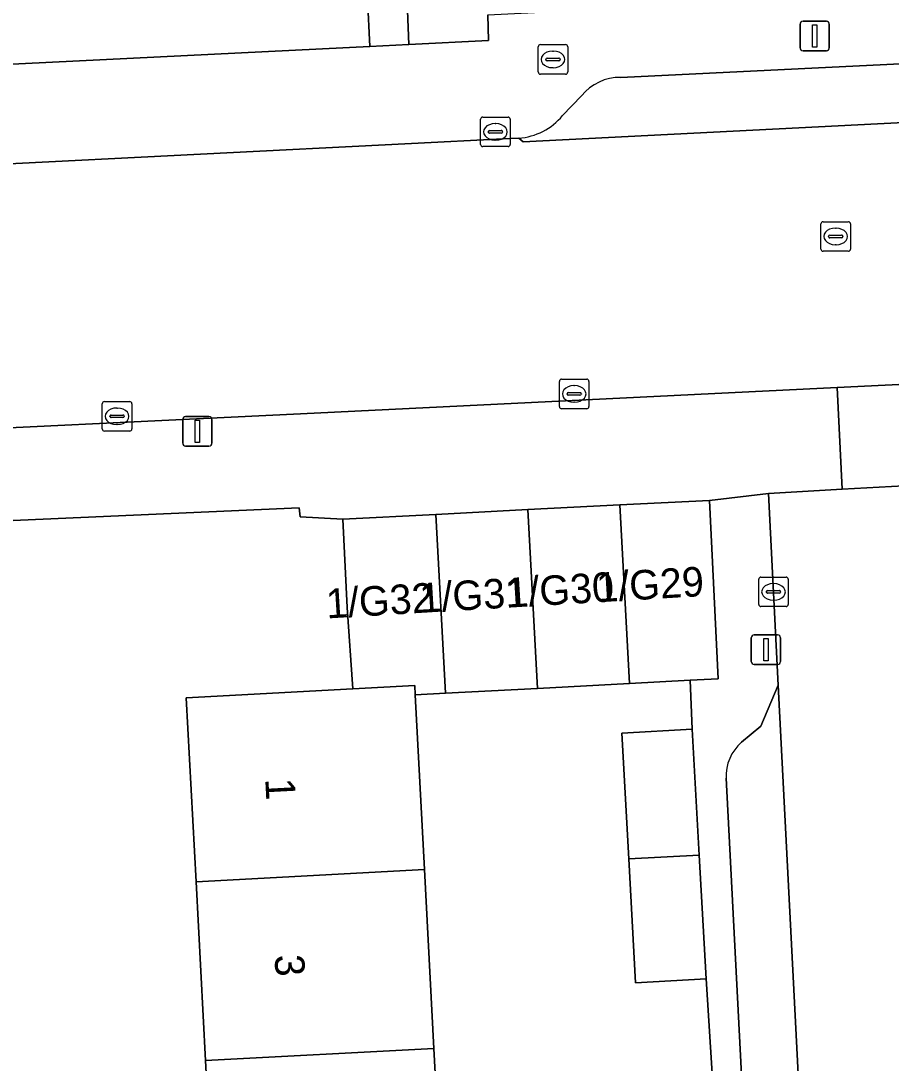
# Model space of a CAD drawing. Extents: x 161084 to 161928, y 385354 to 386522.
# Drawn here: x 161364.66 to 161394.1, y 385718 to 385753.28 of the extents above; entities that cross this region are included whole.
import ezdxf

# ---------------------------------------------------------------- set-up
doc = ezdxf.new("R2010")
doc.units = 0
for name, color, linetype in [('IMGEO_Brandkraan', 7, 'Continuous'), ('IMGEO_Erf', 7, 'Continuous'), ('IMGEO_Kolk', 7, 'Continuous'), ('IMGEO_Lichtmast', 7, 'Continuous'), ('IMGEO_Pand', 7, 'Continuous'), ('IMGEO_Pand_nummerreeks', 7, 'Continuous'), ('IMGEO_Parkeervlak_open', 7, 'Continuous'), ('IMGEO_Rijbaan_lokaal_gesloten', 7, 'Continuous'), ('IMGEO_Rijbaan_lokaal_open', 7, 'Continuous'), ('IMGEO_Rioolput', 7, 'Continuous'), ('IMGEO_Voetpad_open', 7, 'Continuous')]:
    doc.layers.add(name, color=color, linetype=linetype)

msp = doc.modelspace()

# ---------------------------------------------------------------- linework, layer by layer
at = {"layer": 'IMGEO_Brandkraan'}
for p, q in [((161382.162, 385751.55), (161382.162, 385752.402)), ((161382.237, 385752.476), (161383.089, 385752.476)), ((161382.65, 385752.256), (161382.675, 385752.256)), ((161383.163, 385752.402), (161383.163, 385751.55)), ((161382.421, 385751.97), (161382.421, 385751.982)), ((161382.859, 385751.933), (161382.461, 385751.933)), ((161382.464, 385752.019), (161382.862, 385752.019)), ((161382.905, 385751.982), (161382.905, 385751.97)), ((161383.089, 385751.476), (161382.237, 385751.476)), ((161382.673, 385751.696), (161382.648, 385751.696))]:
    msp.add_line(p, q, dxfattribs=at)
for points in [[(161382.162, 385751.55), (161382.162, 385752.402)], [(161382.237, 385752.476), (161383.089, 385752.476)], [(161383.163, 385752.402), (161383.163, 385751.55)], [(161383.089, 385751.476), (161382.237, 385751.476)]]:
    msp.add_lwpolyline(points, dxfattribs=at)
for centre, radius, start, end in [((161382.239, 385752.4), 0.0765, 91.552, 178.448), ((161382.239, 385752.4), 0.0765, 91.552, 178.448), ((161383.087, 385752.4), 0.0765, 1.552, 88.448), ((161383.087, 385752.4), 0.0765, 1.552, 88.448), ((161382.461, 385751.979), 0.0403, 85.8775, 175.7526), ((161382.458, 385751.969), 0.0366, 178.938, 274.7102), ((161382.862, 385751.976), 0.043, 264.8664, 352.4533), ((161382.866, 385751.981), 0.0386, 1.7309, 96.639), ((161382.239, 385751.552), 0.0765, 181.552, 268.448), ((161382.239, 385751.552), 0.0765, 181.552, 268.448), ((161383.087, 385751.552), 0.0765, 271.552, 358.448), ((161383.087, 385751.552), 0.0765, 271.552, 358.448)]:
    msp.add_arc(centre, radius, start, end, dxfattribs=at)
for centre, major_axis, ratio, start_param, end_param in [((161382.649, 385751.976), (-0.387, 0.002), 0.722429, 4.712389, 7.853982), ((161382.674, 385751.976), (-0.39, 0.002), 0.717154, 1.570796, 4.712389)]:
    msp.add_ellipse(centre, major_axis=major_axis, ratio=ratio, start_param=start_param, end_param=end_param, dxfattribs=at)
at = {"layer": 'IMGEO_Erf'}
for points in [[(161453.458, 385766.91), (161450.05, 385766.74), (161450.26, 385762.549), (161443.836, 385762.228), (161437.572, 385761.916), (161431.308, 385761.603), (161425.044, 385761.29), (161418.78, 385760.978), (161412.515, 385760.665), (161406.251, 385760.353), (161399.987, 385760.04), (161393.723, 385759.727), (161387.459, 385759.415), (161381.035, 385759.094), (161380.824, 385763.331), (161377.364, 385763.158), (161377.787, 385752.478), (161380.483, 385752.611), (161380.46, 385753.49), (161418.265, 385755.389), (161453.943, 385757.182)], [(161376.23, 385757.297), (161370.105, 385756.987), (161364.158, 385756.686), (161358.21, 385756.385), (161352.263, 385756.083), (161346.316, 385755.782), (161340.368, 385755.481), (161334.421, 385755.18), (161328.473, 385754.879), (161322.352, 385754.569), (161322.529, 385749.751), (161327.583, 385750), (161376.462, 385752.413)]]:
    msp.add_lwpolyline(points, close=True, dxfattribs=at)
for points in [[(161371.228, 385712.042), (161370.908, 385718.094), (161370.588, 385724.145), (161370.258, 385730.371), (161375.892, 385730.669), (161375.703, 385733.42), (161375.549, 385736.416), (161374.107, 385736.499), (161374.079, 385736.804), (161361.079, 385736.228)], [(161388.083, 385717.128), (161387.843, 385720.857), (161385.457, 385720.724), (161385.224, 385724.918), (161384.988, 385729.175), (161387.375, 385729.308), (161387.301, 385730.962), (161385.248, 385730.853), (161382.135, 385730.689), (161379.021, 385730.524), (161378, 385730.47), (161378.313, 385724.553), (161378.634, 385718.502), (161378.954, 385712.45)]]:
    msp.add_lwpolyline(points, dxfattribs=at)
at = {"layer": 'IMGEO_Kolk'}
for p, q in [((161380.215, 385749.098), (161380.215, 385749.95)), ((161380.29, 385750.024), (161381.142, 385750.024)), ((161380.703, 385749.804), (161380.728, 385749.804)), ((161381.216, 385749.95), (161381.216, 385749.098)), ((161380.474, 385749.518), (161380.474, 385749.53)), ((161380.912, 385749.481), (161380.514, 385749.481)), ((161380.517, 385749.567), (161380.915, 385749.567)), ((161380.958, 385749.53), (161380.958, 385749.518)), ((161381.142, 385749.024), (161380.29, 385749.024)), ((161380.726, 385749.244), (161380.701, 385749.244)), ((161382.879, 385740.228), (161382.879, 385741.08)), ((161382.954, 385741.154), (161383.806, 385741.154)), ((161383.367, 385740.934), (161383.392, 385740.934)), ((161383.88, 385741.08), (161383.88, 385740.228)), ((161383.138, 385740.648), (161383.138, 385740.66)), ((161383.576, 385740.611), (161383.178, 385740.611)), ((161383.181, 385740.697), (161383.579, 385740.697)), ((161383.622, 385740.66), (161383.622, 385740.648)), ((161367.416, 385739.47), (161367.416, 385740.322)), ((161367.491, 385740.396), (161368.343, 385740.396)), ((161367.904, 385740.176), (161367.929, 385740.176)), ((161368.417, 385740.322), (161368.417, 385739.47)), ((161383.39, 385740.374), (161383.365, 385740.374)), ((161367.675, 385739.89), (161367.675, 385739.902)), ((161368.113, 385739.853), (161367.715, 385739.853)), ((161367.718, 385739.939), (161368.116, 385739.939)), ((161368.159, 385739.902), (161368.159, 385739.89)), ((161383.806, 385740.154), (161382.954, 385740.154)), ((161367.927, 385739.616), (161367.902, 385739.616)), ((161368.343, 385739.396), (161367.491, 385739.396)), ((161389.621, 385733.529), (161389.621, 385734.381)), ((161389.696, 385734.455), (161390.548, 385734.455)), ((161390.109, 385734.235), (161390.134, 385734.235)), ((161390.622, 385734.381), (161390.622, 385733.529)), ((161389.88, 385733.949), (161389.88, 385733.961)), ((161390.318, 385733.912), (161389.92, 385733.912)), ((161389.923, 385733.998), (161390.321, 385733.998)), ((161390.364, 385733.961), (161390.364, 385733.949)), ((161390.132, 385733.675), (161390.107, 385733.675)), ((161390.548, 385733.455), (161389.696, 385733.455))]:
    msp.add_line(p, q, dxfattribs=at)
for points in [[(161380.215, 385749.098), (161380.215, 385749.95)], [(161380.29, 385750.024), (161381.142, 385750.024)], [(161381.216, 385749.95), (161381.216, 385749.098)], [(161381.142, 385749.024), (161380.29, 385749.024)], [(161382.879, 385740.228), (161382.879, 385741.08)], [(161382.954, 385741.154), (161383.806, 385741.154)], [(161383.88, 385741.08), (161383.88, 385740.228)], [(161367.416, 385739.47), (161367.416, 385740.322)], [(161367.491, 385740.396), (161368.343, 385740.396)], [(161368.417, 385740.322), (161368.417, 385739.47)], [(161383.806, 385740.154), (161382.954, 385740.154)], [(161368.343, 385739.396), (161367.491, 385739.396)], [(161389.621, 385733.529), (161389.621, 385734.381)], [(161389.696, 385734.455), (161390.548, 385734.455)], [(161390.622, 385734.381), (161390.622, 385733.529)], [(161390.548, 385733.455), (161389.696, 385733.455)]]:
    msp.add_lwpolyline(points, dxfattribs=at)
for centre, radius, start, end in [((161380.292, 385749.948), 0.0765, 91.552, 178.448), ((161380.292, 385749.948), 0.0765, 91.552, 178.448), ((161381.14, 385749.948), 0.0765, 1.552, 88.448), ((161381.14, 385749.948), 0.0765, 1.552, 88.448), ((161380.514, 385749.527), 0.0403, 85.8775, 175.7526), ((161380.511, 385749.517), 0.0366, 178.938, 274.7102), ((161380.915, 385749.524), 0.043, 264.8664, 352.4533), ((161380.919, 385749.529), 0.0386, 1.7309, 96.639), ((161380.292, 385749.1), 0.0765, 181.552, 268.448), ((161380.292, 385749.1), 0.0765, 181.552, 268.448), ((161381.14, 385749.1), 0.0765, 271.552, 358.448), ((161381.14, 385749.1), 0.0765, 271.552, 358.448), ((161382.956, 385741.078), 0.0765, 91.552, 178.448), ((161382.956, 385741.078), 0.0765, 91.552, 178.448), ((161383.804, 385741.078), 0.0765, 1.552, 88.448), ((161383.804, 385741.078), 0.0765, 1.552, 88.448), ((161383.178, 385740.657), 0.0403, 85.8775, 175.7526), ((161383.175, 385740.647), 0.0366, 178.938, 274.7102), ((161383.579, 385740.654), 0.043, 264.8664, 352.4533), ((161383.583, 385740.659), 0.0386, 1.7309, 96.639), ((161367.493, 385740.32), 0.0765, 91.552, 178.448), ((161367.493, 385740.32), 0.0765, 91.552, 178.448), ((161368.341, 385740.32), 0.0765, 1.552, 88.448), ((161368.341, 385740.32), 0.0765, 1.552, 88.448), ((161382.956, 385740.23), 0.0765, 181.552, 268.448), ((161382.956, 385740.23), 0.0765, 181.552, 268.448), ((161383.804, 385740.23), 0.0765, 271.552, 358.448), ((161383.804, 385740.23), 0.0765, 271.552, 358.448), ((161367.715, 385739.899), 0.0403, 85.8775, 175.7526), ((161367.712, 385739.889), 0.0366, 178.938, 274.7102), ((161368.116, 385739.896), 0.043, 264.8664, 352.4533), ((161368.12, 385739.901), 0.0386, 1.7309, 96.639), ((161367.493, 385739.472), 0.0765, 181.552, 268.448), ((161367.493, 385739.472), 0.0765, 181.552, 268.448), ((161368.341, 385739.472), 0.0765, 271.552, 358.448), ((161368.341, 385739.472), 0.0765, 271.552, 358.448), ((161389.698, 385734.379), 0.0765, 91.552, 178.448), ((161389.698, 385734.379), 0.0765, 91.552, 178.448), ((161390.546, 385734.379), 0.0765, 1.552, 88.448), ((161390.546, 385734.379), 0.0765, 1.552, 88.448), ((161389.92, 385733.958), 0.0403, 85.8775, 175.7526), ((161389.917, 385733.948), 0.0366, 178.938, 274.7102), ((161390.321, 385733.955), 0.043, 264.8664, 352.4533), ((161390.325, 385733.96), 0.0386, 1.7309, 96.639), ((161389.698, 385733.531), 0.0765, 181.552, 268.448), ((161389.698, 385733.531), 0.0765, 181.552, 268.448), ((161390.546, 385733.531), 0.0765, 271.552, 358.448), ((161390.546, 385733.531), 0.0765, 271.552, 358.448)]:
    msp.add_arc(centre, radius, start, end, dxfattribs=at)
for centre, major_axis, ratio, start_param, end_param in [((161380.702, 385749.524), (-0.387, 0.002), 0.722429, 4.712389, 7.853982), ((161380.727, 385749.524), (-0.39, 0.002), 0.717154, 1.570796, 4.712389), ((161383.366, 385740.654), (-0.387, 0.002), 0.722429, 4.712389, 7.853982), ((161383.391, 385740.654), (-0.39, 0.002), 0.717154, 1.570796, 4.712389), ((161367.903, 385739.896), (-0.387, 0.002), 0.722429, 4.712389, 7.853982), ((161367.928, 385739.896), (-0.39, 0.002), 0.717154, 1.570796, 4.712389), ((161390.108, 385733.955), (-0.387, 0.002), 0.722429, 4.712389, 7.853982), ((161390.133, 385733.955), (-0.39, 0.002), 0.717154, 1.570796, 4.712389)]:
    msp.add_ellipse(centre, major_axis=major_axis, ratio=ratio, start_param=start_param, end_param=end_param, dxfattribs=at)
at = {"layer": 'IMGEO_Lichtmast'}
for p, q in [((161391.121, 385753.269), (161391.911, 385753.269)), ((161391.911, 385753.269), (161391.121, 385753.269)), ((161391.021, 385752.369), (161391.021, 385753.169)), ((161391.021, 385753.169), (161391.021, 385752.369)), ((161392.011, 385753.169), (161392.011, 385752.369)), ((161392.011, 385752.369), (161392.011, 385753.169)), ((161391.911, 385752.269), (161391.121, 385752.269)), ((161391.121, 385752.269), (161391.911, 385752.269)), ((161370.236, 385739.888), (161371.026, 385739.888)), ((161371.026, 385739.888), (161370.236, 385739.888)), ((161370.136, 385738.988), (161370.136, 385739.788)), ((161370.136, 385739.788), (161370.136, 385738.988)), ((161371.126, 385739.788), (161371.126, 385738.988)), ((161371.126, 385738.988), (161371.126, 385739.788)), ((161371.026, 385738.888), (161370.236, 385738.888)), ((161370.236, 385738.888), (161371.026, 385738.888)), ((161389.471, 385732.498), (161390.261, 385732.498)), ((161390.261, 385732.498), (161389.471, 385732.498)), ((161389.371, 385731.598), (161389.371, 385732.398)), ((161389.371, 385732.398), (161389.371, 385731.598)), ((161390.361, 385732.398), (161390.361, 385731.598)), ((161390.361, 385731.598), (161390.361, 385732.398)), ((161390.261, 385731.498), (161389.471, 385731.498)), ((161389.471, 385731.498), (161390.261, 385731.498))]:
    msp.add_line(p, q, dxfattribs=at)
for points in [[(161391.441, 385753.144), (161391.591, 385753.144), (161391.591, 385752.394), (161391.441, 385752.394), (161391.441, 385753.144)], [(161370.556, 385739.763), (161370.706, 385739.763), (161370.706, 385739.013), (161370.556, 385739.013), (161370.556, 385739.763)], [(161389.791, 385732.373), (161389.941, 385732.373), (161389.941, 385731.623), (161389.791, 385731.623), (161389.791, 385732.373)]]:
    msp.add_lwpolyline(points, dxfattribs=at)
for centre, start, end in [((161391.121, 385753.169), 90, 180), ((161391.121, 385753.169), 90, 180), ((161391.911, 385753.169), 0, 90), ((161391.911, 385753.169), 360, 90), ((161391.121, 385752.369), 180, 270), ((161391.121, 385752.369), 180, 270), ((161391.911, 385752.369), 270, 0), ((161391.911, 385752.369), 270, 0), ((161370.236, 385739.788), 90, 180), ((161370.236, 385739.788), 90, 180), ((161371.026, 385739.788), 0, 90), ((161371.026, 385739.788), 360, 90), ((161370.236, 385738.988), 180, 270), ((161370.236, 385738.988), 180, 270), ((161371.026, 385738.988), 270, 0), ((161371.026, 385738.988), 270, 0), ((161389.471, 385732.398), 90, 180), ((161389.471, 385732.398), 90, 180), ((161390.261, 385732.398), 0, 90), ((161390.261, 385732.398), 360, 90), ((161389.471, 385731.598), 180, 270), ((161389.471, 385731.598), 180, 270), ((161390.261, 385731.598), 270, 0), ((161390.261, 385731.598), 270, 0)]:
    msp.add_arc(centre, 0.1, start, end, dxfattribs=at)
at = {"layer": 'IMGEO_Pand'}
for points in [[(161387.962, 385737.051), (161384.929, 385736.896), (161385.248, 385730.853), (161387.301, 385730.962), (161388.254, 385731.012)], [(161381.815, 385736.737), (161378.701, 385736.577), (161379.021, 385730.524), (161382.135, 385730.689)], [(161384.929, 385736.896), (161381.815, 385736.737), (161382.135, 385730.689), (161385.248, 385730.853)], [(161378.701, 385736.577), (161375.549, 385736.416), (161375.703, 385733.42), (161375.892, 385730.669), (161377.984, 385730.78), (161378, 385730.47), (161379.021, 385730.524)], [(161377.984, 385730.78), (161375.892, 385730.669), (161370.258, 385730.371), (161370.588, 385724.145), (161378.313, 385724.553), (161378, 385730.47)], [(161387.375, 385729.308), (161384.988, 385729.175), (161385.224, 385724.918), (161387.611, 385725.044)], [(161387.611, 385725.044), (161385.224, 385724.918), (161385.457, 385720.724), (161387.843, 385720.857)], [(161378.634, 385718.502), (161378.313, 385724.553), (161370.588, 385724.145), (161370.908, 385718.094)], [(161370.908, 385718.094), (161371.228, 385712.042), (161378.954, 385712.45), (161378.634, 385718.502)]]:
    msp.add_lwpolyline(points, close=True, dxfattribs=at)
at = {"layer": 'IMGEO_Parkeervlak_open'}
for points in [[(161530.283, 385758.789), (161528.955, 385758.728), (161500.001, 385757.213), (161458.938, 385755.138), (161455.76, 385754.979), (161454.163, 385754.884), (161450.803, 385754.684), (161418.419, 385752.994), (161384.956, 385751.367)], [(161381.504, 385749.31), (161381.651, 385749.181), (161418.736, 385751.073), (161500.103, 385755.198)], [(161383.628, 385750.746), (161382.99, 385750.073)], [(161393.58, 385666.612), (161393.423, 385669.684), (161393.28, 385672.47), (161390.284, 385730.795), (161389.69, 385729.412), (161389.045, 385728.863)], [(161388.519, 385727.644), (161391.505, 385669.795)]]:
    msp.add_lwpolyline(points, dxfattribs=at)
for centre, radius, start, end in [((161384.928, 385749.697), 1.67, 89.0274, 141.0961), ((161381.342, 385751.454), 2.15, 274.3196, 320.0376), ((161390.018, 385727.72), 1.501, 130.4156, 182.9039)]:
    msp.add_arc(centre, radius, start, end, dxfattribs=at)
at = {"layer": 'IMGEO_Rijbaan_lokaal_gesloten'}
for points in [[(161500.103, 385755.198), (161418.736, 385751.073), (161381.651, 385749.181), (161381.504, 385749.31), (161380.98, 385749.285), (161377.878, 385749.133), (161320.765, 385746.237), (161317.001, 385746.046), (161299.32, 385745.062), (161299.179, 385744.92), (161280.571, 385744.018), (161280.109, 385744.015), (161242.513, 385742.169), (161236.694, 385741.875), (161234.962, 385741.865), (161229.395, 385741.609), (161215.298, 385740.905), (161214.505, 385740.872), (161212.577, 385740.786), (161211.091, 385740.701), (161207.545, 385740.541), (161206.729, 385740.502), (161202.497, 385740.278)], [(161219.21, 385731.574), (161226.143, 385732.277), (161227.672, 385732.492), (161228.871, 385732.544), (161235.991, 385732.925), (161235.882, 385734.948), (161276.893, 385737.129), (161276.964, 385735.09), (161280.741, 385735.276), (161299.274, 385736.216), (161307.516, 385736.632), (161344.089, 385738.537), (161374.123, 385739.983), (161392.28, 385740.871), (161410.143, 385741.745), (161419.016, 385742.246), (161440.186, 385743.38), (161458.492, 385744.297), (161476.551, 385745.201), (161500, 385746.526), (161506.744, 385746.859), (161524.82, 385747.75), (161543.029, 385748.648), (161566.659, 385749.814)]]:
    msp.add_lwpolyline(points, dxfattribs=at)
at = {"layer": 'IMGEO_Rijbaan_lokaal_open'}
msp.add_lwpolyline([(161390.284, 385730.795), (161393.28, 385672.47), (161398.285, 385672.728), (161395.274, 385731.281), (161394.951, 385737.565), (161392.451, 385737.426), (161389.951, 385737.287)], close=True, dxfattribs=at)
at = {"layer": 'IMGEO_Rioolput'}
for p, q in [((161391.727, 385745.557), (161391.727, 385746.409)), ((161391.802, 385746.483), (161392.654, 385746.483)), ((161392.215, 385746.263), (161392.24, 385746.263)), ((161392.728, 385746.409), (161392.728, 385745.557)), ((161391.986, 385745.977), (161391.986, 385745.989)), ((161392.424, 385745.94), (161392.026, 385745.94)), ((161392.029, 385746.026), (161392.427, 385746.026)), ((161392.47, 385745.989), (161392.47, 385745.977)), ((161392.654, 385745.483), (161391.802, 385745.483)), ((161392.238, 385745.703), (161392.213, 385745.703))]:
    msp.add_line(p, q, dxfattribs=at)
for points in [[(161391.727, 385745.557), (161391.727, 385746.409)], [(161391.802, 385746.483), (161392.654, 385746.483)], [(161392.728, 385746.409), (161392.728, 385745.557)], [(161392.654, 385745.483), (161391.802, 385745.483)]]:
    msp.add_lwpolyline(points, dxfattribs=at)
for centre, radius, start, end in [((161391.804, 385746.407), 0.0765, 91.552, 178.448), ((161391.804, 385746.407), 0.0765, 91.552, 178.448), ((161392.652, 385746.407), 0.0765, 1.552, 88.448), ((161392.652, 385746.407), 0.0765, 1.552, 88.448), ((161392.026, 385745.986), 0.0403, 85.8775, 175.7526), ((161392.023, 385745.976), 0.0366, 178.938, 274.7102), ((161392.427, 385745.983), 0.043, 264.8664, 352.4533), ((161392.431, 385745.988), 0.0386, 1.7309, 96.639), ((161391.804, 385745.559), 0.0765, 181.552, 268.448), ((161391.804, 385745.559), 0.0765, 181.552, 268.448), ((161392.652, 385745.559), 0.0765, 271.552, 358.448), ((161392.652, 385745.559), 0.0765, 271.552, 358.448)]:
    msp.add_arc(centre, radius, start, end, dxfattribs=at)
for centre, major_axis, ratio, start_param, end_param in [((161392.214, 385745.983), (-0.387, 0.002), 0.722429, 4.712389, 7.853982), ((161392.239, 385745.983), (-0.39, 0.002), 0.717154, 1.570796, 4.712389)]:
    msp.add_ellipse(centre, major_axis=major_axis, ratio=ratio, start_param=start_param, end_param=end_param, dxfattribs=at)
at = {"layer": 'IMGEO_Voetpad_open'}
for points in [[(161376.23, 385757.297), (161376.462, 385752.413), (161377.787, 385752.478), (161377.364, 385763.158)], [(161384.956, 385751.367), (161418.419, 385752.994), (161450.803, 385754.684)], [(161380.46, 385753.49), (161380.483, 385752.611), (161377.787, 385752.478), (161376.462, 385752.413), (161327.583, 385750), (161322.529, 385749.751), (161320.944, 385749.672), (161299.076, 385748.593), (161293.511, 385748.193)], [(161382.99, 385750.073), (161383.628, 385750.746)], [(161298.907, 385745.045), (161299.32, 385745.062), (161317.001, 385746.046), (161320.765, 385746.237), (161377.878, 385749.133), (161380.98, 385749.285), (161381.504, 385749.31)], [(161440.186, 385743.38), (161419.016, 385742.246), (161410.143, 385741.745), (161392.28, 385740.871), (161392.451, 385737.426), (161394.951, 385737.565), (161396.862, 385737.493), (161400.076, 385737.654), (161403.163, 385737.808), (161406.25, 385737.963), (161409.253, 385738.113), (161410.311, 385738.223), (161410.302, 385738.711), (161419.2, 385739.135)], [(161352.929, 385735.735), (161361.079, 385736.228), (161374.079, 385736.804), (161374.107, 385736.499), (161375.549, 385736.416), (161378.701, 385736.577), (161381.815, 385736.737), (161384.929, 385736.896), (161387.962, 385737.051), (161389.951, 385737.287), (161392.451, 385737.426), (161392.28, 385740.871), (161374.123, 385739.983), (161344.089, 385738.537), (161307.516, 385736.632), (161299.274, 385736.216)], [(161389.045, 385728.863), (161389.69, 385729.412), (161390.284, 385730.795), (161389.951, 385737.287), (161387.962, 385737.051), (161388.254, 385731.012), (161387.301, 385730.962), (161387.375, 385729.308), (161387.611, 385725.044), (161387.843, 385720.857), (161388.083, 385717.128)], [(161391.505, 385669.795), (161388.519, 385727.644)]]:
    msp.add_lwpolyline(points, dxfattribs=at)
for centre, radius, start, end in [((161384.928, 385749.697), 1.67, 89.0274, 141.0961), ((161381.342, 385751.454), 2.15, 274.3196, 320.0376), ((161390.018, 385727.72), 1.501, 130.4156, 182.9039)]:
    msp.add_arc(centre, radius, start, end, dxfattribs=at)

# ---------------------------------------------------------------- texts
at = {"layer": 'IMGEO_Pand_nummerreeks'}
for s, rotation, p in [('1/G30', 3.4263, (161381.117, 385733.418)), ('1/G29', 3.4263, (161384.158, 385733.6)), ('1/G32', 3.4263, (161375.014, 385733.053)), ('1/G31', 3.4263, (161378.177, 385733.243)), ('1', 273.0305, (161372.927, 385727.625)), ('3', 273.0305, (161373.243, 385721.658))]:
    msp.add_text(s, height=1, rotation=rotation, dxfattribs=at).set_placement(p)

doc.saveas('drawing.dxf')
